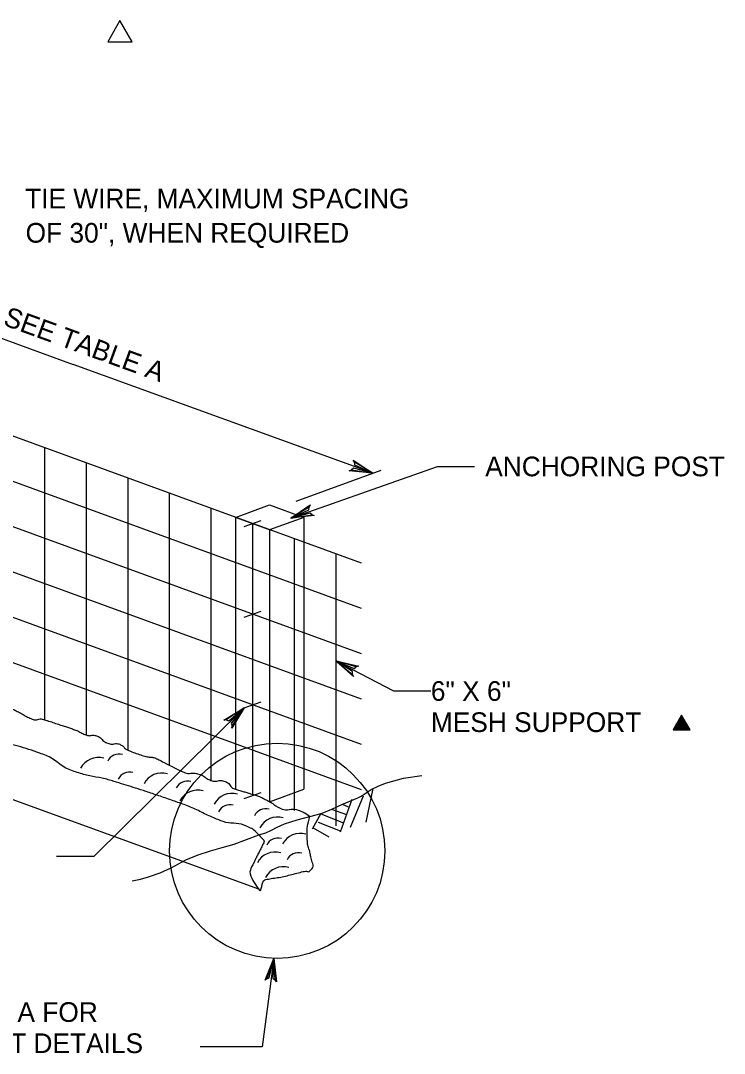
# Model space of a CAD drawing. Extents: x 636462 to 639049, y 299944 to 300538.
# Drawn here: x 636637.5 to 636744.8, y 300112.8 to 300270.2 of the extents above; entities that cross this region are included whole.
import ezdxf

# ---------------------------------------------------------------- set-up
doc = ezdxf.new("R2010")
doc.units = 0
doc.layers.add('Default', color=7, linetype='Continuous')

msp = doc.modelspace()

# ---------------------------------------------------------------- linework, layer by layer
at = {"layer": 'Default'}
for p, q in [((636689.45, 300187.5), (636613.62, 300215.1)), ((636689.45, 300180.59), (636616.89, 300207)), ((636641.13, 300205.09), (636641.13, 300163.65)), ((636641.13, 300205.09), (636641.13, 300205.09)), ((636647.48, 300202.78), (636647.48, 300161.34)), ((636647.48, 300202.78), (636647.48, 300202.78)), ((636679.48, 300196.93), (636692.46, 300201.66)), ((636653.83, 300200.47), (636653.83, 300159.03)), ((636653.83, 300200.47), (636653.83, 300200.47)), ((636689.45, 300173.69), (636620.24, 300198.88)), ((636660.17, 300198.16), (636660.17, 300156.72)), ((636660.17, 300198.16), (636660.17, 300198.16)), ((636666.52, 300195.85), (636666.52, 300154.41)), ((636666.52, 300195.85), (636666.52, 300195.85)), ((636670.27, 300194.48), (636670.27, 300153.04)), ((636680.65, 300194.48), (636680.65, 300153.04)), ((636671.57, 300193.07), (636674.16, 300194.01)), ((636672.86, 300193.54), (636672.86, 300152.1)), ((636672.86, 300193.54), (636672.86, 300193.54)), ((636689.45, 300166.78), (636621.71, 300191.44)), ((636675.46, 300192.59), (636675.46, 300151.15)), ((636679.21, 300191.23), (636679.21, 300149.79)), ((636679.21, 300191.23), (636679.21, 300191.23)), ((636685.56, 300188.92), (636685.56, 300147.48)), ((636685.56, 300188.92), (636685.56, 300188.92)), ((636689.45, 300159.87), (636621.74, 300184.52)), ((636673.8, 300137.8), (636559.57, 300179.37)), ((636671.57, 300179.25), (636674.16, 300180.2)), ((636672.86, 300179.73), (636672.86, 300179.73)), ((636689.45, 300152.97), (636624.4, 300176.65)), ((636671.57, 300165.44), (636674.16, 300166.38)), ((636672.86, 300165.91), (636672.86, 300165.91)), ((636737.98, 300162.11), (636737.47, 300163)), ((636738.1, 300162.11), (636737.53, 300163.11)), ((636738.22, 300162.11), (636737.59, 300163.21)), ((636738.34, 300162.11), (636737.65, 300163.31)), ((636738.46, 300162.11), (636737.71, 300163.42)), ((636738.58, 300162.11), (636737.77, 300163.52)), ((636738.7, 300162.11), (636737.83, 300163.62)), ((636738.82, 300162.11), (636737.89, 300163.73)), ((636738.94, 300162.11), (636737.95, 300163.83)), ((636739.06, 300162.11), (636738.01, 300163.93)), ((636739.18, 300162.11), (636738.07, 300164.04)), ((636739.3, 300162.11), (636738.13, 300164.14)), ((636739.42, 300162.11), (636738.19, 300164.24)), ((636739.54, 300162.11), (636738.25, 300164.35)), ((636737.03, 300162.11), (636736.99, 300162.17)), ((636737.15, 300162.11), (636737.05, 300162.28)), ((636737.27, 300162.11), (636737.11, 300162.38)), ((636737.39, 300162.11), (636737.17, 300162.48)), ((636737.51, 300162.11), (636737.23, 300162.59)), ((636737.63, 300162.11), (636737.29, 300162.69)), ((636737.75, 300162.11), (636737.35, 300162.79)), ((636737.87, 300162.11), (636737.41, 300162.9)), ((636671.57, 300151.62), (636674.16, 300152.57)), ((636675.46, 300151.15), (636680.65, 300153.04)), ((636687.76, 300147.26), (636689.79, 300152.06)), ((636690.17, 300148.06), (636691.23, 300153.15)), ((636686.27, 300146.54), (636688.02, 300151.54)), ((636686.54, 300150.79), (636687.6, 300150.33)), ((636681.59, 300148.92), (636681.59, 300148.92)), ((636681.98, 300147.04), (636683.32, 300149.4)), ((636683.27, 300149.3), (636686.72, 300147.95)), ((636684.91, 300150.02), (636687.19, 300149.22)), ((636682.84, 300148.05), (636686.21, 300146.73)), ((636682.08, 300147.19), (636684.46, 300145.81))]:
    msp.add_line(p, q, dxfattribs=at)
for points in [[(636650.78, 300266.94), (636654.51, 300266.94), (636652.65, 300270.17)], [(636675.46, 300192.59), (636670.27, 300194.48), (636675.46, 300196.37), (636680.65, 300194.48)], [(636736.96, 300162.11), (636739.55, 300162.11), (636738.25, 300164.35)]]:
    msp.add_lwpolyline(points, close=True, dxfattribs=at)
for points in [[(636614.68, 300229.04), (636645.53, 300217.77)], [(636691.18, 300201.2), (636645.53, 300217.77)], [(636688.37, 300202.9), (636688.19, 300203.21), (636691.18, 300201.2), (636688.37, 300202.9), (636688.42, 300202.49), (636691.18, 300201.2), (636688.25, 300201.99), (636687.95, 300201.7), (636691.18, 300201.2), (636687.6, 300201.56), (636687.95, 300201.7)], [(636678.68, 300194.34), (636701.03, 300202.25), (636706.7, 300202.25)], [(636681.93, 300194.86), (636682.26, 300194.75), (636678.68, 300194.34), (636681.93, 300194.86), (636681.62, 300195.14), (636678.68, 300194.34), (636681.43, 300195.63), (636681.47, 300196.05), (636678.68, 300194.34), (636681.65, 300196.38), (636681.47, 300196.05)], [(636688.11, 300170.56), (636688.24, 300170.24), (636685.53, 300172.62), (636688.11, 300170.56), (636688.1, 300170.99), (636685.53, 300172.62), (636688.34, 300171.45), (636688.67, 300171.7), (636685.53, 300172.62), (636689.04, 300171.8), (636688.67, 300171.7)], [(636685.53, 300172.62), (636694.34, 300168.06), (636700.01, 300168.06)], [(636671.57, 300165.44), (636648.65, 300142.8), (636642.98, 300142.8)], [(636668.82, 300163.61), (636668.48, 300163.58), (636671.57, 300165.44), (636668.82, 300163.61), (636669.23, 300163.49), (636671.57, 300165.44), (636669.6, 300163.12), (636669.73, 300162.72), (636671.57, 300165.44), (636669.71, 300162.34), (636669.73, 300162.72)], [(636654.53, 300139.07), (636655.77, 300139.35), (636657, 300139.7), (636658.76, 300140.33), (636660.47, 300141.06), (636661.59, 300141.69), (636662.71, 300142.31), (636664.55, 300143.04), (636666.44, 300143.67), (636668.24, 300144.16), (636670.04, 300144.67), (636671.92, 300145.37), (636673.8, 300146.09), (636674.34, 300146.24), (636674.88, 300146.41), (636675.76, 300146.83), (636676.62, 300147.27), (636677.18, 300147.53), (636677.74, 300147.77), (636679.65, 300148.39), (636681.59, 300148.92), (636682.53, 300149.14), (636683.45, 300149.39), (636684.96, 300150.04), (636686.44, 300150.75), (636687.68, 300151.24), (636688.92, 300151.75), (636689.43, 300152.02), (636690.91, 300152.99), (636692, 300153.53), (636693.14, 300153.98), (636695.88, 300154.75), (636698.67, 300155.14)], [(636676.11, 300127.28), (636674.32, 300113.78), (636664.87, 300113.78)], [(636675.01, 300124.17), (636674.76, 300123.94), (636676.11, 300127.28), (636675.01, 300124.17), (636675.41, 300124.31), (636676.11, 300127.28), (636675.93, 300124.25), (636676.28, 300124.01), (636676.11, 300127.28), (636676.49, 300123.7), (636676.28, 300124.01)]]:
    msp.add_lwpolyline(points, dxfattribs=at)
msp.add_circle((636676.62, 300143.67), 16.4, dxfattribs=at)
for centre, radius, start, end in [((636652.52, 300156.44), 1.96, 75.3044, 152.6271), ((636649.37, 300154.78), 3.11, 74.7812, 151.5772), ((636654.14, 300153.7), 1.96, 75.3044, 152.6271), ((636659.06, 300152.42), 3.11, 74.7812, 151.5772), ((636662.96, 300152.34), 1.96, 75.3044, 152.6271), ((636664.52, 300149.81), 3.11, 74.7812, 151.5772), ((636669.74, 300149.32), 3.11, 74.7812, 151.5772), ((636669.42, 300148.73), 1.96, 75.3044, 152.6271), ((636674.88, 300148.11), 1.96, 75.3044, 152.6271), ((636676.7, 300145.71), 3.11, 74.7812, 151.5772), ((636680.18, 300143.23), 3.11, 74.7812, 151.5772), ((636676.75, 300143.64), 1.96, 75.3044, 152.6271), ((636676.33, 300140.37), 3.11, 74.7812, 151.5772), ((636679.85, 300141.41), 1.96, 75.3044, 152.6271), ((636677.57, 300138.14), 3.11, 74.7812, 151.5772)]:
    msp.add_arc(centre, radius, start, end, dxfattribs=at)
for points in [[(636567.43, 300190.47), (636568.26, 300189.86), (636569.1, 300189.31), (636570.04, 300188.89), (636572.02, 300188), (636574.04, 300187.26), (636576.13, 300186.78), (636577.32, 300186.5), (636578.52, 300186.28), (636579.72, 300186), (636580.68, 300185.78), (636581.63, 300185.53), (636582.59, 300185.29), (636584.13, 300184.89), (636585.61, 300184.31), (636587.06, 300183.67), (636588.23, 300183.16), (636588.97, 300181.88), (636590.17, 300181.43), (636591.75, 300180.84), (636593.43, 300180.54), (636595.01, 300179.94), (636595.88, 300179.62), (636596.74, 300179.26), (636597.62, 300178.95), (636599.64, 300178.24), (636601.67, 300177.53), (636603.7, 300176.84), (636604.94, 300176.42), (636606.19, 300176), (636607.43, 300175.6), (636608.58, 300175.22), (636609.77, 300174.98), (636610.91, 300174.6), (636612.29, 300174.15), (636613.65, 300173.63), (636615.01, 300173.11), (636616.47, 300172.56), (636617.91, 300171.96), (636619.36, 300171.37), (636620.69, 300170.83), (636621.89, 300169.96), (636623.21, 300169.39), (636624.02, 300169.03), (636625.06, 300169.46), (636625.89, 300169.19), (636626.33, 300169.05), (636626.63, 300168.54), (636627.06, 300168.39), (636627.48, 300168.24), (636628.02, 300168.43), (636628.44, 300168.26), (636629.06, 300168.02), (636629.51, 300167.33), (636630.16, 300167.15), (636631.06, 300166.9), (636632, 300166.78), (636632.9, 300166.53), (636633.53, 300166.35), (636634.17, 300166.2), (636634.79, 300165.96), (636635.55, 300165.65), (636636.27, 300165.27), (636637, 300164.91), (636637.71, 300164.56), (636638.38, 300164.12), (636639.11, 300163.8), (636639.73, 300163.52), (636640.49, 300163.86), (636641.13, 300163.65), (636641.99, 300163.37), (636642.85, 300163.09), (636643.7, 300162.8), (636644.33, 300162.6), (636644.95, 300162.39), (636645.57, 300162.18), (636646.23, 300161.96), (636646.83, 300161.58), (636647.48, 300161.34), (636647.97, 300161.15), (636648.55, 300161.34), (636649.05, 300161.19), (636649.69, 300160.99), (636650.16, 300160.3), (636650.78, 300160.07), (636651.39, 300159.84), (636652.18, 300160.1), (636652.77, 300159.82), (636653.17, 300159.64), (636653.42, 300159.2), (636653.83, 300159.03), (636654.7, 300158.66), (636655.59, 300158.34), (636656.5, 300158.08), (636657.07, 300157.92), (636657.7, 300157.96), (636658.24, 300157.71), (636658.89, 300157.4), (636659.52, 300157.04), (636660.17, 300156.72)], [(636673.8, 300146.09), (636673.35, 300146.57), (636672.87, 300147.01), (636672.27, 300147.27), (636670.81, 300147.93), (636669.14, 300147.81), (636667.68, 300148.39), (636665.76, 300149.16), (636663.92, 300150.19), (636661.96, 300150.88), (636660.03, 300151.56), (636658.08, 300152.23), (636656.13, 300152.86), (636654.68, 300153.34), (636653.23, 300153.78), (636651.78, 300154.23), (636649.95, 300154.8), (636648.02, 300155.02), (636646.19, 300155.6), (636644.1, 300156.25), (636642.41, 300157.85), (636640.35, 300158.58), (636638.76, 300159.14), (636637.13, 300159.61), (636635.51, 300160.07), (636633.54, 300160.62), (636631.49, 300160.81), (636629.54, 300161.44), (636627.99, 300161.94), (636626.85, 300163.35), (636625.32, 300163.92), (636622.84, 300164.85), (636620.36, 300165.76), (636617.87, 300166.65), (636615.88, 300167.37), (636613.89, 300168.07), (636611.9, 300168.76), (636610.1, 300169.39), (636608.12, 300169.38), (636606.32, 300170.01), (636604.86, 300170.51), (636603.79, 300171.85), (636602.34, 300172.37), (636599.42, 300173.4), (636596.44, 300174.3), (636593.52, 300175.35), (636591.7, 300176), (636589.88, 300176.69), (636588.06, 300177.34), (636586.39, 300177.93), (636584.64, 300178.26), (636582.96, 300178.83), (636581.37, 300179.37), (636579.95, 300180.38), (636578.36, 300180.94), (636576.22, 300181.7), (636573.9, 300181.96), (636571.78, 300182.8), (636570.33, 300183.38), (636568.89, 300183.96), (636567.44, 300184.54), (636564.81, 300185.58), (636562.19, 300186.62), (636559.57, 300187.66)], [(636660.17, 300156.72), (636660.85, 300156.38), (636661.53, 300156.04), (636662.21, 300155.72), (636662.97, 300155.37), (636663.91, 300155.59), (636664.7, 300155.35), (636665.34, 300155.16), (636665.89, 300154.62), (636666.52, 300154.41), (636667.18, 300154.18), (636668.01, 300154.49), (636668.67, 300154.23), (636669.28, 300153.99), (636669.63, 300153.23), (636670.27, 300153.04), (636670.9, 300152.86), (636671.52, 300152.68), (636672.15, 300152.49), (636672.56, 300152.37), (636672.98, 300152.25), (636673.39, 300152.12), (636674.12, 300151.89), (636674.78, 300151.5), (636675.46, 300151.15), (636675.96, 300150.9), (636676.37, 300150.5), (636676.87, 300150.26), (636677.84, 300149.78), (636679.08, 300150.16), (636680.1, 300149.76), (636680.63, 300149.55), (636681.13, 300149.28), (636681.59, 300148.92)], [(636673.8, 300146.09), (636674.2, 300145.67), (636674.73, 300145.23), (636674.51, 300144.79), (636674.18, 300144.13), (636673.85, 300143.47), (636673.52, 300142.8), (636673.27, 300142.31), (636673.02, 300141.81), (636672.77, 300141.31), (636672.23, 300140.22), (636673.18, 300138.76), (636673.8, 300137.8), (636674.13, 300137.28), (636674.38, 300139.2), (636675.01, 300139.32), (636675.94, 300139.51), (636676.93, 300139.6), (636677.86, 300139.82), (636678.86, 300140.06), (636679.85, 300140.33), (636680.85, 300140.57), (636681.09, 300140.62), (636681.36, 300140.41), (636681.59, 300140.63), (636682.29, 300141.3), (636681.83, 300142.18), (636681.71, 300142.93), (636681.6, 300143.63), (636681.27, 300144.33), (636681.22, 300145.04), (636681.13, 300146.31), (636681.21, 300147.65), (636681.59, 300148.92)]]:
    msp.add_open_spline(points, degree=3, dxfattribs=at)

# ---------------------------------------------------------------- texts
for s, p in [('TIE WIRE, MAXIMUM SPACING', (636638.19, 300241.56)), ('OF 30", WHEN REQUIRED', (636638.27, 300236.34)), ('ANCHORING POST', (636708.32, 300200.74)), ('6" X 6"', (636700.03, 300166.52)), ('MESH SUPPORT', (636700.03, 300161.77)), ('SEE DETAIL A FOR', (636612.74, 300117.6)), ('EMBEDMENT DETAILS', (636612.74, 300112.85))]:
    msp.add_text(s, height=2.998, dxfattribs=at).set_placement(p)
msp.add_text('SEE TABLE A', height=2.998, rotation=340, dxfattribs=at).set_placement((636634.69, 300223.83))

doc.saveas('drawing.dxf')
